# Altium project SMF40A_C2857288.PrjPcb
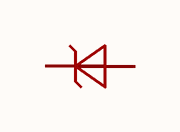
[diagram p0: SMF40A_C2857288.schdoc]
1 sheet, 1 parts. Net scope: global (net labels, ports and power ports of the same name join across sheets).

## Sheet SMF40A_C2857288.schdoc
size 127 x 101 mm

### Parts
D?  smf40a_c2857288  [SOD-123FL_L2.7-W1.8-LS3.7-RD]  (value not drawn)

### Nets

Not connected (* = marked no-connect by the designer): D? 1 2

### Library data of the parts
D? = smf40a_c2857288: 极性:单向;反向截止电压(Vrwm):40V;钳位电压:64.5V;峰值脉冲电流(Ipp):3.1A;峰值脉冲功率(Ppp):200W@10/1000us;击穿电压(VBR):44.4V;; Manufacturer: JSMSEMI(杰盛微); ManufacturerPart: SMF40A; AddInBom: yes; ModelId: 86f9151e155e4fe2af0c4f2e0a80302e; ModelName: SOD-123FL_L2.8-W1.8-H1.1-LS3.6; ModelTransform: 141.732,70.866,0,180,0,0,0,0,0; Polarity: 单向; Reverse Stand-Off Voltage (Vrwm): 40V; Clamping Voltage: 64.5V; Peak Pulse Current (Ipp): 3.1A; Voltage - Breakdown: 44.4V; Reverse Leakage Current (Ir): 1uA; Number of Channels: 单路; Type: TVS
